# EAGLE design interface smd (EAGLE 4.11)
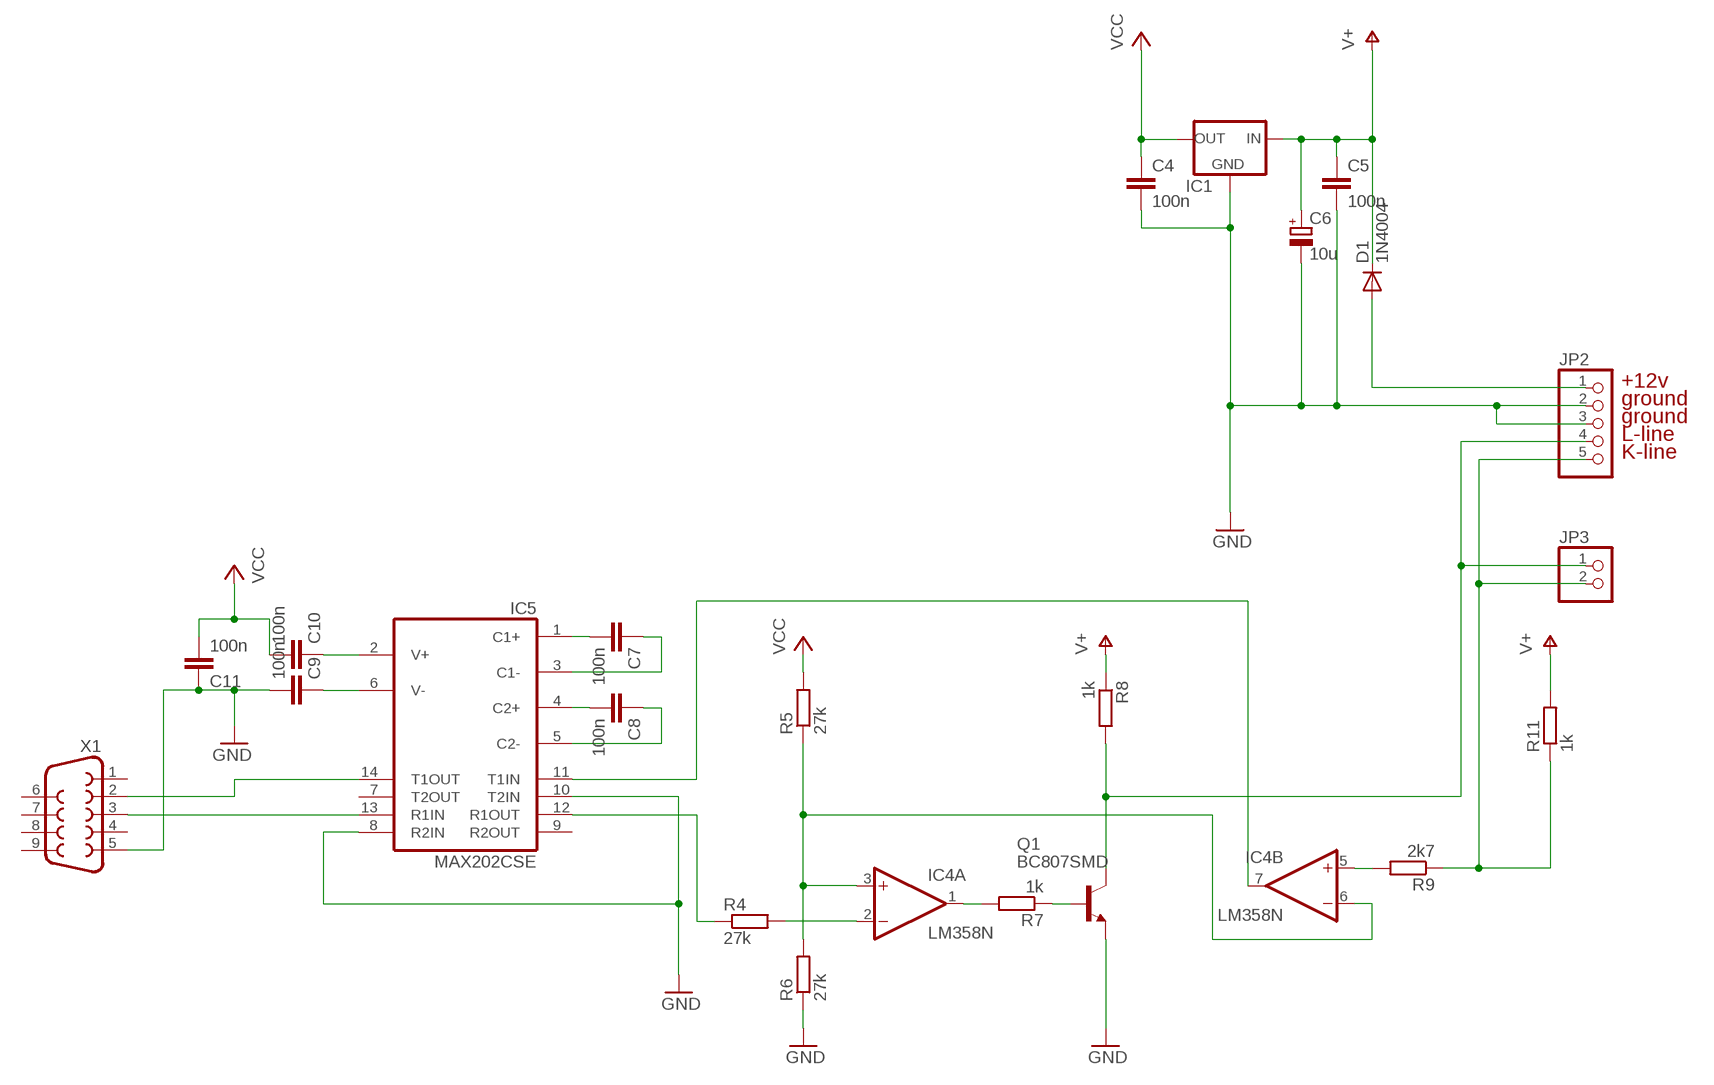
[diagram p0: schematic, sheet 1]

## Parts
C4  100n  C-EUC0805  [C0805]
C5  100n  C-EUC0805  [C0805]
C6  10u  CPOL-EUC  [PANASONIC_C]
C7  100n  C-EUC0805  [C0805]
C8  100n  C-EUC0805  [C0805]
C9  100n  C-EUC0805  [C0805]
C10  100n  C-EUC0805  [C0805]
C11  100n  C-EUC0805  [C0805]
D1  1N4004  [DO41-10]
IC1  78LXX  [78LXX]
IC4  LM358N  LF353D  [SO08]
IC5  MAX202CSE  [SO16]
JP2  PINHD-1X5  [1X05]
JP3  PINHD-1X2  [1X02]
Q1  BC807SMD  [SOT23-BEC]
R4  27k  R-EU_M0805  [M0805]
R5  27k  R-EU_M0805  [M0805]
R6  27k  R-EU_M0805  [M0805]
R7  1k  R-EU_M0805  [M0805]
R8  1k  R-EU_M0805  [M0805]
R9  2k7  R-EU_M0805  [M0805]
R11  1k  R-EU_M0805  [M0805]
X1  F09HP  [F09HP]

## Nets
GND: C4.2 C5.2 C6.- C9.2 C11.1 IC1.GND IC5.8(R2IN) IC5.10(T2IN) JP2.2 JP2.3 Q1.E R6.1 X1.5
N$14: D1.A JP2.1
N$15: JP2.5 JP3.2 R9.1 R11.1
N$20: C7.2 IC5.1(C1+)
N$21: C8.1 IC5.5(C2-)
N$22: C7.1 IC5.3(C1-)
N$23: C8.2 IC5.4(C2+)
N$24: C10.1 IC5.2(V+)
N$25: IC5.13(R1IN) X1.3
N$26: C9.1 IC5.6(V-)
N$27: IC4.3(A:+IN) IC4.6(B:-IN) R5.1 R6.2
N$28: IC5.14(T1OUT) X1.2
N$29: IC4.2(A:-IN) R4.2
N$30: IC4.1(A:OUT) R7.2
N$31: Q1.B R7.1
N$32: IC4.7(B:OUT) IC5.11(T1IN)
N$33: JP2.4 JP3.1 Q1.C R8.2
N$35: IC4.5(B:+IN) R9.2
N$50: IC5.12(R1OUT) R4.1
V+: C5.1 C6.+ D1.C IC1.IN R8.1 R11.2
VCC: C4.1 C10.2 C11.2 IC1.OUT R5.2
Unconnected: IC5.7(T2OUT) IC5.9(R2OUT) X1.1 X1.4 X1.6 X1.7 X1.8 X1.9

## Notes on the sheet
- +12v
- ground
- ground
- L-line
- K-line

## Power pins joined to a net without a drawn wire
GND: IC4.4(GND) IC5.15(GND)
VCC: IC4.8(VCC) IC5.16(VCC)

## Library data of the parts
C4 C5 C7-C11 = rcl:C-EU: CAPACITOR, European symbol
C6 = rcl:CPOL-EU: POLARIZED CAPACITOR, European symbol
D1 = diode:1N4004: DIODE
IC1 = v-reg:78LXX: VOLTAGE REGULATOR
IC4 = linear:LF353: OP AMP
IC5 = maxim:MAX202CSE
JP2 = pinhead:PINHD-1X5: PIN HEADER
JP3 = pinhead:PINHD-1X2: PIN HEADER
Q1 = transistor-npn:BC807*: NPN Transistor
R4-R9 R11 = rcl:R-EU_: RESISTOR, European symbol
X1 = con-subd:F09: SUB-D

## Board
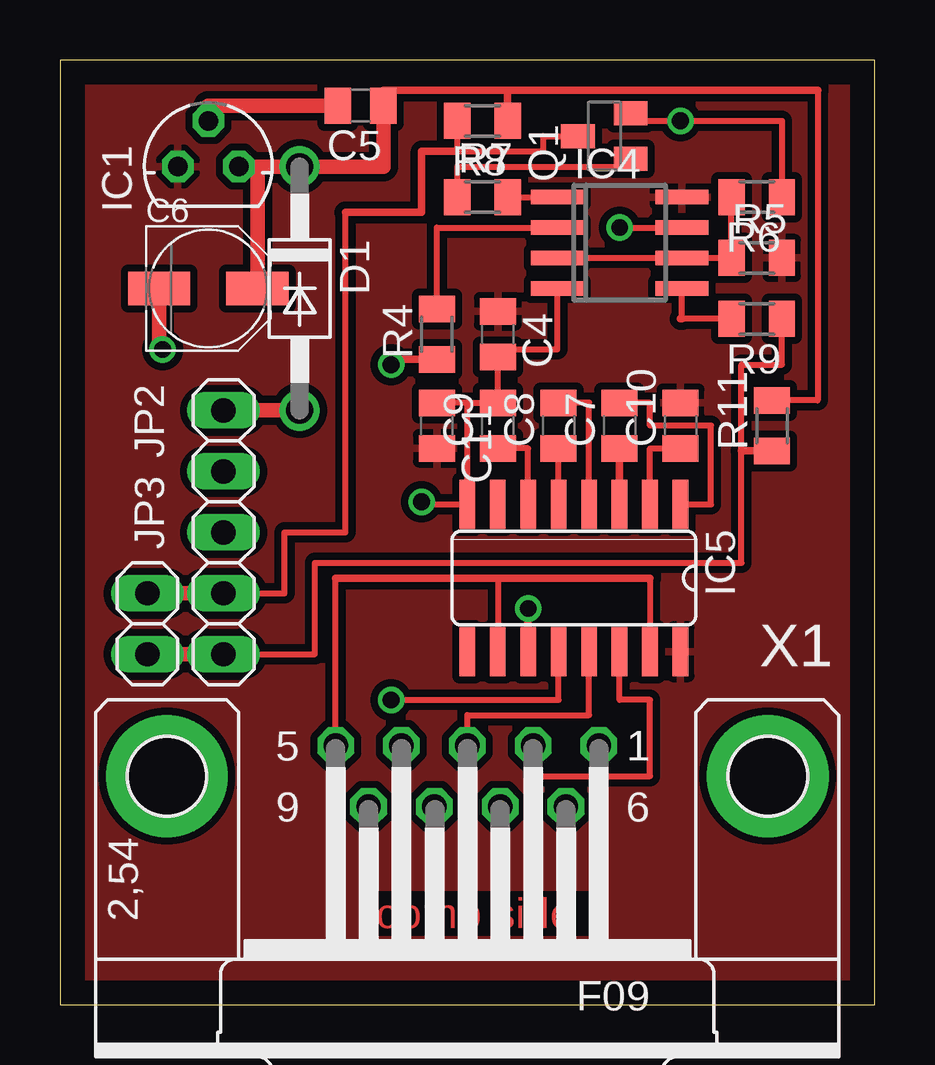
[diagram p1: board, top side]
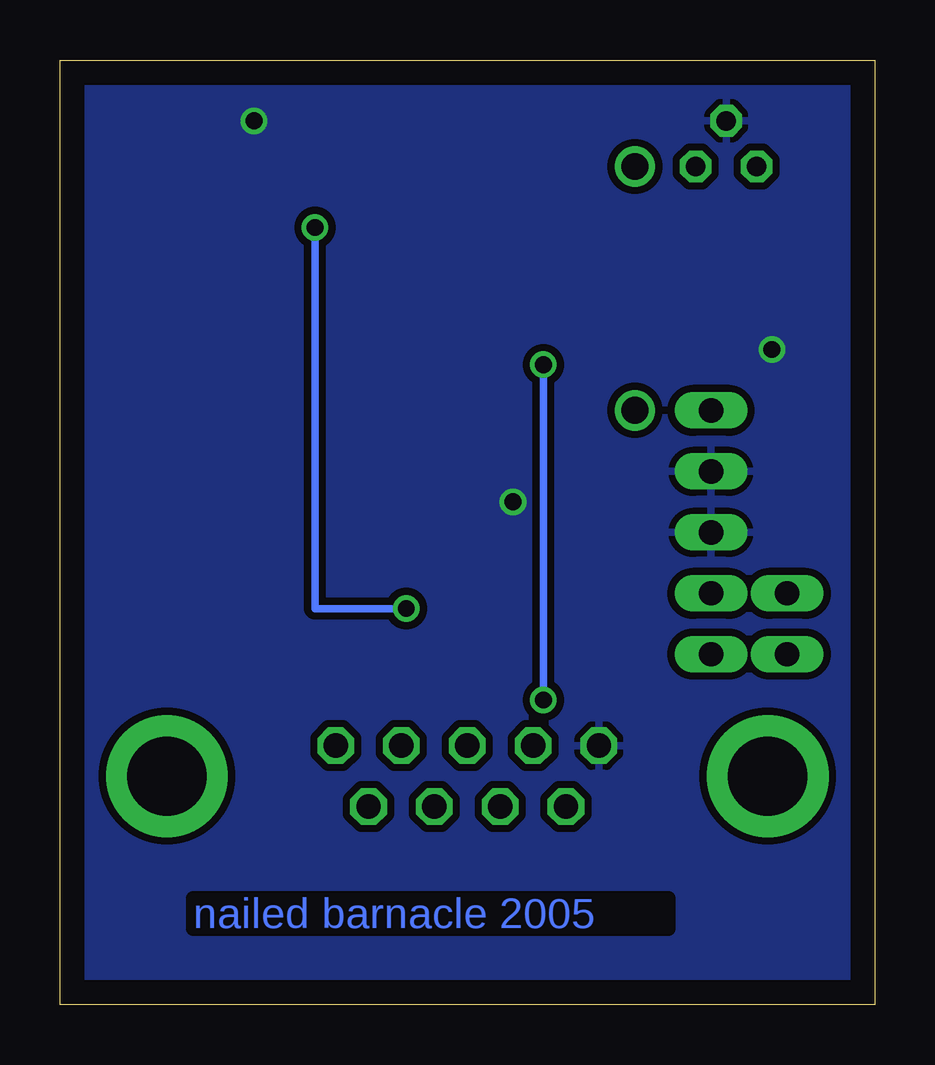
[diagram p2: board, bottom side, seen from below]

Size 33.96 x 39.36 mm. Coordinates in mm from the lower left corner, seen from the top.
Outline: 0,0 33.96,0 33.96,39.36 0,39.36 0,0
Copper layers (1*16): Top 0.035mm / dielectric 1.5mm / Bottom 0.035mm
Design rules "10mils": minimum track width 10mil, minimum drill 24mil, track to track 10mil, track to pad 10mil, pad to pad 10mil, via to via 10mil, smd to smd 10mil, copper to edge 40mil, drill to drill 10mil, minimum pad ring 10mil, minimum via ring 8mil, stop-mask expansion 0mil, vias tented up to drill 0mil, thermal gap 10mil

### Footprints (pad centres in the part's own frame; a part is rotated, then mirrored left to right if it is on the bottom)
C0805 = smd 1.1 x 1.5: 1 -0.95,0; 2 0.95,0
PANASONIC_C = smd 2.6 x 1.4: + 2.05,0; - -2.05,0
DO41-10 = drill 1.118 round: A 5.08,0; C -5.08,0
78LXX = drill 0.813 octagon: GND 0,1.905; IN 1.27,0; OUT -1.27,0
SO08 = smd 0.6 x 2.2: 1 -1.905,-2.6; 2 -0.635,-2.6; 3 0.635,-2.6; 4 1.905,-2.6; 5 1.905,2.6; 6 0.635,2.6; 7 -0.635,2.6; 8 -1.905,2.6
SO16 = smd 0.66 x 2.032: 1 -4.445,-3.073; 2 -3.175,-3.073; 3 -1.905,-3.073; 4 -0.635,-3.073; 5 0.635,-3.073; 6 1.905,-3.073; 7 3.175,-3.073; 8 4.445,-3.073; 9 4.445,3.073; 10 3.175,3.073; 11 1.905,3.073; 12 0.635,3.073; 13 -0.635,3.073; 14 -1.905,3.073; 15 -3.175,3.073; 16 -4.445,3.073
1X05 = drill 1.016 long: 1 -5.08,0; 2 -2.54,0; 3 0,0; 4 2.54,0; 5 5.08,0
1X02 = drill 1.016 long: 1 -1.27,0; 2 1.27,0
SOT23-BEC = smd 1 x 1.4: B -0.95,-1.1; C 0,1.1; E 0.95,-1.1
M0805 = smd 1.1 x 1.5: 1 -1.05,0; 2 1.05,0
F09HP = drill 1.016 octagon: 1 -5.486,-1.27; 2 -2.743,-1.27; 3 0,-1.27; 4 2.743,-1.27; 5 5.486,-1.27; 6 -4.115,1.27; 7 -1.372,1.27; 8 1.372,1.27; 9 4.115,1.27 | drill 3.302 pad 5.08 round: G1 -12.522,0; G2 12.522,0

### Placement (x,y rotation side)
C4  18.25,27.93 270 top
C5  12.54,37.46 180 top
C6  6.18,29.84 0 top
C7  23.33,24.12 90 top
C8  20.79,24.12 90 top
C9  18.25,24.12 90 top
C10  25.87,24.12 90 top
C11  15.71,24.12 270 top
D1  10,29.84 270 top
IC1  6.18,34.92 0 top
IC4  23.33,31.74 270 top
IC5  21.42,17.77 180 top
JP2  6.82,19.68 270 top
JP3  3.64,15.87 270 top
Q1  22.7,36.19 90 top
R4  15.71,27.93 90 top
R5  29.04,31.11 0 top
R6  29.04,33.65 180 top
R7  17.61,33.65 0 top
R8  17.61,36.83 180 top
R9  29.04,28.57 180 top
R11  29.68,24.12 90 top
X1  16.98,9.52 180 top

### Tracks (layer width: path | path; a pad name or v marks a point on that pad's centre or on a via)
GND  (via drill 0.7)
  Top 0.254: 24.6,17.77 IC5.15 | 18.25,17.77 IC5.10 | X1.5 11.49,17.77 | 15.08,20.85 IC5.8 16.98,25.07 | 16.98,25.07 C9.2 C4.2 | 16.98,25.07 C11.1 | R6.1 30.09,36.83 v25.87,36.83 23.79,36.83 | IC4.4 20.73,27.3 18.25,27.3
  Top 0.305: v4.28,27.3 4.13,27.3 | 24.6,17.77 18.25,17.77 11.49,17.77 | IC5.10 18.25,14.6 | 15.08,20.85 v15.08,20.95 | C4.2 18.25,27.3 | Q1.E 23.79,36.83
  Top 0.61: 4.13,27.3 C6.- | IC1.GND 6.18,37.46 C5.2
  pour Bottom (isolate 0.305): 0.47,0.63 33.49,0.63 33.49,38.73 0.47,38.73
N$14
  Top 0.61: JP2.1 D1.A
N$15
  Top 0.254: R9.1 30.09,26.66 28.41,26.66 28.41,23.07 28.41,18.41 10.63,18.41 10.63,14.6 JP2.5
  Top 0.305: 28.41,23.07 R11.1
  Top 0.61: JP3.2 JP2.5
N$20
  Top 0.254: IC5.1 27.14,20.85 27.14,24.12 24.6,24.12 24.6,25.07 C7.2
N$21
  Top 0.254: IC5.5 C8.1
N$22
  Top 0.305: 23.33,23.49 C7.1 IC5.3
N$23
  Top 0.254: C8.2 22.06,25.08 IC5.4
N$24
  Top 0.254: C10.1 24.6,23.18 IC5.2
N$25
  Top 0.254: X1.3 16.98,12.06 22.06,12.06 IC5.13
N$26
  Top 0.254: C9.1 19.52,23.18 IC5.6
N$27
  Top 0.254: IC4.3 IC4.6 R5.1 R6.2
N$28
  Top 0.254: X1.2 19.72,9.52 24.6,9.52 24.6,12.7 23.33,12.7 IC5.14
N$29
  Top 0.254: IC4.2 15.71,32.38 R4.2
N$30
  Top 0.254: R7.2 IC4.1
N$31
  Top 0.254: R7.1 16.56,34.92 23.79,34.92
  Top 0.305: 23.96,34.92 23.79,34.92 Q1.B
N$32  (via drill 0.7)
  Top 0.254: v23.33,32.38 IC4.7
  Top 0.305: 19.52,14.6 IC5.11 v19.52,16.5
  Bottom 0.305: v23.33,32.38 23.33,16.5 v19.52,16.5
N$33
  Top 0.254: JP2.4 9.36,17.14 9.36,19.68 11.9,19.68 11.9,33.02 | 16.34,35.55 20.15,35.55 20.15,36.19 Q1.C | 16.56,35.55 R8.2
  Top 0.305: 11.9,33.02 15.08,33.02 15.08,35.55 16.34,35.55 16.56,35.55
  Top 0.61: JP3.1 JP2.4
N$35
  Top 0.254: IC4.5 25.93,28.57 R9.2
  Top 0.305: 25.93,28.57 25.87,28.57
N$50  (via drill 0.7)
  Top 0.254: IC5.12 20.79,12.7 v13.81,12.7
  Top 0.305: R4.1 13.81,26.88 v13.81,26.66
  Bottom 0.305: v13.81,12.7 v13.81,26.66
V+
  Top 0.254: R11.2 31.58,25.18 31.58,38.1
  Top 0.305: C5.1 13.49,38.1 18.88,38.1 | 18.88,38.1 31.58,38.1 | R8.1 18.66,38.1 18.88,38.1
  Top 0.61: C6.+ 8.23,34.92 8.09,34.92 | 8.09,34.92 IC1.IN | 8.09,34.92 D1.C 13.49,34.92 C5.1
VCC
  pour Top (isolate 0.305): 0.47,0.63 33.49,0.63 33.49,38.73 0.47,38.73

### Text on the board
Top: comp side
Bottom: nailed barnacle 2005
